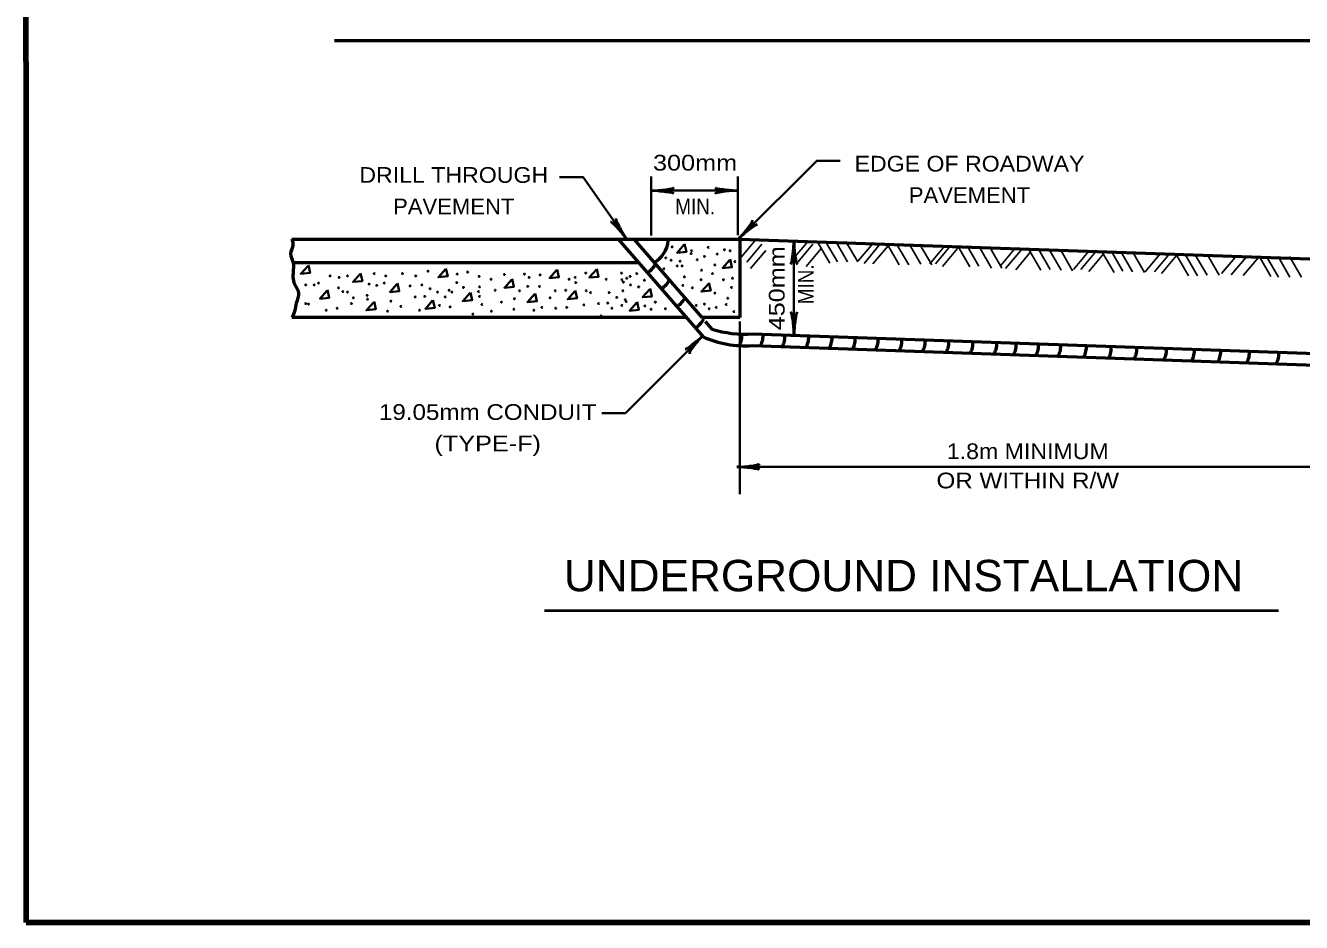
# Model space of a CAD drawing. Extents: x -90 to 623, y -379 to 75.
# Drawn here: x -42.6 to 119.8, y -369 to -254.8 of the extents above; entities that cross this region are included whole.
import ezdxf
from ezdxf.enums import TextEntityAlignment as Align

# ---------------------------------------------------------------- set-up
doc = ezdxf.new("R2010")
doc.units = 0
doc.header["$LTSCALE"] = 0.8
doc.layers.add('1', color=7, linetype='Continuous', lineweight=35)

msp = doc.modelspace()

# ---------------------------------------------------------------- linework, layer by layer
at = {"layer": '1', "lineweight": 53}
for p, q in [((-3.2295, -256.7077), (194.5145, -256.7077)), ((32.8492, -281.9895), (43.6675, -294.4345)), ((34.8368, -281.9895), (43.5093, -291.966)), ((48.3367, -281.9895), (123.3002, -284.6073)), ((-8.6632, -284.9895), (35.4571, -284.9895)), ((41.4103, -291.9895), (-8.6632, -291.9895)), ((48.3367, -291.9895), (43.5063, -291.9895)), ((43.9508, -292.4741), (44.7996, -293.4504)), ((49.9544, -294.0532), (122.8722, -296.5997)), ((49.9021, -295.5523), (122.8199, -298.0987))]:
    msp.add_line(p, q, dxfattribs=at)
at = {"layer": '1'}
for p, q in [((37.076, -281.52), (37.076, -274.02)), ((48.076, -281.5199), (48.076, -274.0199)), ((37.076, -275.8309), (48.076, -275.8309)), ((55.2352, -282.3041), (55.2352, -294.1794)), ((48.3342, -292.4785), (48.3342, -314.4785)), ((47.9859, -310.9966), (123.3332, -310.9966))]:
    msp.add_line(p, q, dxfattribs=at)
at = {"layer": '1', "lineweight": 25}
for p, q in [((50.2675, -282.2197), (48.3392, -284.518)), ((57.0807, -282.2197), (55.1523, -284.518)), ((58.2869, -282.45), (59.7869, -285.0481)), ((59.2602, -282.2878), (60.7602, -284.8858)), ((60.558, -282.2878), (62.058, -284.8858)), ((61.8558, -282.2878), (63.3558, -284.8858)), ((65.3537, -282.463), (63.4254, -284.7613)), ((51.1597, -282.6252), (49.2313, -284.9235)), ((51.6463, -283.4362), (49.718, -285.7346)), ((57.6484, -282.6252), (55.7201, -284.9235)), ((58.7028, -283.1929), (56.7745, -285.4912)), ((66.0837, -282.7874), (64.1554, -285.0858)), ((67.2193, -282.8685), (65.2909, -285.1668)), ((67.1278, -282.6933), (68.6278, -285.2914)), ((68.3445, -282.6933), (69.8445, -285.2914)), ((69.8856, -282.6122), (71.3856, -285.2102)), ((71.2644, -282.6933), (72.7644, -285.2914)), ((74.438, -282.8685), (72.5097, -285.1668)), ((75.168, -282.8685), (73.2397, -285.1668)), ((76.0602, -283.1929), (74.1318, -285.4912)), ((76.1309, -282.9366), (77.6309, -285.5347)), ((77.2665, -282.8555), (78.7665, -285.4536)), ((78.8887, -283.0988), (80.3887, -285.6969)), ((80.1864, -283.0988), (81.6864, -285.6969)), ((83.4411, -283.1118), (81.5127, -285.4102)), ((84.09, -283.4362), (82.1617, -285.7346)), ((85.3877, -283.5985), (83.4594, -285.8968)), ((85.1341, -283.3422), (86.6341, -285.9402)), ((86.3507, -283.2611), (87.8507, -285.8592)), ((87.7295, -283.3422), (89.2295, -285.9402)), ((89.1895, -283.4232), (90.6895, -286.0213)), ((92.7281, -283.5579), (90.7998, -285.8562)), ((93.6608, -283.5579), (91.7325, -285.8562)), ((94.6747, -283.8418), (92.7463, -286.1402)), ((94.4616, -283.6666), (95.9616, -286.2647)), ((95.5971, -283.5044), (97.0971, -286.1025)), ((96.8137, -283.5855), (98.3137, -286.1836)), ((98.3548, -283.6666), (99.8548, -286.2647)), ((101.8528, -283.8823), (99.9245, -286.1807)), ((103.0289, -283.8823), (101.1006, -286.1807)), ((103.9212, -284.0852), (101.9928, -286.3835)), ((103.9513, -284.0722), (105.4513, -286.6703)), ((105.0869, -284.0722), (106.5869, -286.6703)), ((106.3035, -283.9911), (107.8035, -286.5892)), ((107.8446, -283.9911), (109.3446, -286.5892)), ((111.586, -284.0852), (109.6577, -286.3835)), ((114.4145, -284.1533), (115.9145, -286.7513)), ((112.8026, -284.2473), (110.8742, -286.5457)), ((114.3437, -284.3285), (112.4153, -286.6268)), ((115.3877, -284.2343), (116.8877, -286.8324)), ((116.8477, -284.2343), (118.3477, -286.8324)), ((118.3077, -284.2343), (119.8077, -286.8324))]:
    msp.add_line(p, q, dxfattribs=at)
at = {"layer": '1', "lineweight": 40}
msp.add_line((23.5023, -329.2931), (116.8997, -329.2931), dxfattribs=at)
at = {"layer": '1', "lineweight": 158}
msp.add_line((617.1938, -368.9978), (-42.4728, -368.9978), dxfattribs=at)
msp.add_lwpolyline([(617.1938, 69.4188), (-42.5562, 69.3355), (-42.4728, -368.9978)], dxfattribs=at)
at = {"layer": '1'}
for points in [[(48.2287, -281.9152), (58.1283, -272.0157), (61.1283, -272.0157)], [(33.8785, -281.9368), (28.391, -274.0997), (25.391, -274.0997)], [(41.2724, -282.6997), (40.3511, -283.7362), (41.5411, -283.621), (41.3107, -282.6229)], [(-6.6018, -285.3831), (-7.5231, -286.4196), (-6.3331, -286.3044), (-6.5634, -285.3063)], [(10.9013, -285.81), (9.98, -286.8465), (11.17, -286.7313), (10.9397, -285.7332)], [(47.0661, -284.6513), (46.1448, -285.6877), (47.3347, -285.5726), (47.1044, -284.5745)], [(0.0457, -286.4198), (-0.8756, -287.4563), (0.3144, -287.3412), (0.0841, -286.3431)], [(19.3174, -287.1517), (18.3961, -288.1882), (19.5861, -288.073), (19.3558, -287.0749)], [(25.0501, -285.9319), (24.1288, -286.9684), (25.3187, -286.8533), (25.0884, -285.8552)], [(30.1119, -285.871), (29.1906, -286.9075), (30.3806, -286.7923), (30.1502, -285.7942)], [(-4.1623, -288.5543), (-5.0836, -289.5908), (-3.8936, -289.4757), (-4.1239, -288.4776)], [(4.7417, -287.7006), (3.8203, -288.7371), (5.0103, -288.6219), (4.78, -287.6238)], [(14.0116, -288.8592), (13.0902, -289.8957), (14.2802, -289.7806), (14.0499, -288.7825)], [(22.2447, -288.9812), (21.3234, -290.0177), (22.5134, -289.9026), (22.2831, -288.9045)], [(27.3676, -288.6153), (26.4462, -289.6518), (27.6363, -289.5367), (27.4059, -288.5386)], [(36.8814, -288.3714), (35.9601, -289.4079), (37.1501, -289.2928), (36.9198, -288.2947)], [(44.3827, -287.6396), (43.4613, -288.6761), (44.6513, -288.5609), (44.421, -287.5628)], [(1.7533, -290.018), (0.832, -291.0545), (2.022, -290.9393), (1.7917, -289.9412)], [(9.2547, -289.8351), (8.3333, -290.8716), (9.5233, -290.7564), (9.293, -289.7583)], [(35.2347, -290.079), (34.3134, -291.1155), (35.5034, -291.0003), (35.2731, -290.0023)], [(43.6774, -294.2512), (33.7779, -304.1508), (30.7779, -304.1508)]]:
    msp.add_lwpolyline(points, dxfattribs=at)
at = {"layer": '1', "lineweight": 53}
msp.add_lwpolyline([(-8.6632, -281.9895), (48.3367, -281.9895), (48.3367, -291.9895)], dxfattribs=at)
at = {"layer": '1'}
for centre in [(39.7142, -282.9907), (42.1388, -283.8394), (42.1995, -283.4757), (43.8361, -284.2031), (44.321, -283.0513), (45.4727, -283.9), (46.382, -283.3544), (47.1093, -283.4757), (38.6837, -285.7791), (38.9262, -284.3849), (39.593, -284.688), (40.381, -285.4154), (40.7447, -284.8092), (40.9872, -285.4154), (42.9268, -284.6274), (45.1697, -285.2942), (47.7155, -284.8698), (-3.8079, -286.6883), (-2.6562, -286.8702), (-1.5651, -286.6883), (1.8294, -286.3852), (3.2842, -286.6883), (5.4057, -286.3852), (7.1029, -286.6883), (8.679, -286.0822), (12.3765, -286.4458), (13.7101, -286.2034), (15.1648, -286.7489), (16.6803, -287.1127), (18.3775, -286.5065), (20.9233, -286.4458), (21.5295, -286.8702), (22.9237, -286.5671), (26.6212, -287.1127), (27.4093, -286.8702), (28.7427, -286.3246), (31.3492, -287.1127), (33.289, -286.3246), (33.3496, -287.1732), (33.9558, -286.9914), (34.3801, -286.7489), (35.2287, -286.3852), (36.1985, -287.2338), (41.2903, -286.8096), (43.4117, -287.1732), (43.4724, -285.9609), (44.8666, -286.3852), (46.2608, -287.1732), (47.4124, -286.9914), (-6.8992, -287.84), (-5.8082, -287.84), (-5.2627, -287.5976), (-2.7168, -288.2038), (-2.1713, -288.6887), (-1.5651, -288.7493), (1.1626, -287.7188), (2.1325, -287.9007), (3.1023, -287.5976), (6.3756, -287.9613), (7.891, -287.84), (8.9214, -288.3249), (9.8912, -288.7493), (11.3461, -288.5068), (11.7097, -288.7493), (12.3159, -287.5369), (13.1645, -288.1431), (15.1042, -288.6887), (15.2255, -288.0825), (17.2257, -288.5068), (20.3172, -288.5674), (21.3477, -288.0218), (22.8631, -288.0218), (24.8633, -288.5674), (26.1969, -288.5068), (27.4698, -287.5369), (28.8034, -288.5674), (29.3489, -288.8098), (31.7129, -288.8098), (33.4708, -288.5674), (33.5314, -287.4763), (34.4407, -287.84), (35.4712, -288.0825), (41.1084, -287.9007), (42.3207, -288.2038), (45.1697, -288.8705), (47.2912, -288.1431), (-6.8992, -290.204), (-6.5356, -290.2647), (-1.0802, -290.204), (-0.8377, -289.4767), (0.9202, -289.1736), (0.9808, -289.6585), (3.9509, -289.9009), (5.2238, -290.5677), (7.0423, -289.3554), (8.2547, -289.2948), (10.1337, -290.4465), (10.8612, -289.3554), (11.4672, -290.6283), (15.2255, -289.2948), (15.5286, -290.3252), (18.0137, -290.0222), (19.6504, -289.5978), (23.1662, -290.6889), (24.1966, -289.4767), (26.3182, -290.6889), (28.5003, -290.3859), (30.3794, -290.204), (31.5311, -290.1434), (32.6828, -289.416), (33.3496, -290.4465), (33.7739, -289.7191), (33.8951, -289.9616), (36.2592, -290.5071), (37.5927, -290.0222), (39.1081, -289.1736), (42.8057, -290.4465), (43.8361, -290.2647), (45.3515, -290.6889), (46.6244, -290.3252), (46.8062, -289.5372), (-4.2928, -291.0527), (-2.8987, -290.8102), (3.5267, -291.1739), (7.5879, -291.0527), (14.3768, -291.5376), (16.7408, -291.1739), (19.5898, -290.9314), (22.1357, -291.0527), (24.924, -290.8102), (30.6825, -291.78), (32.0767, -290.8102), (37.0472, -290.9314), (38.8656, -290.8708), (44.4423, -290.8708), (47.5942, -291.2345)]:
    msp.add_circle(centre, 0.0607, dxfattribs=at)
at = {"layer": '1', "lineweight": 53}
for centre, radius, start, end in [((35.4988, -281.7617), 3.7689, 301.08152, 353.13064), ((35.5578, -284.3752), 2.1707, 299.00343, 339.84739), ((37.3543, -286.3513), 2.1707, 299.00343, 339.84739), ((39.3305, -288.6269), 2.1707, 299.00343, 339.84739), ((41.6659, -291.3816), 2.1707, 299.00343, 339.84739), ((48.9237, -280.526), 13.5665, 252.30241, 274.35724), ((48.9991, -282.6433), 12.9405, 245.66897, 274.00127), ((46.4423, -294.3473), 2.1707, 327.00343, 7.84739), ((49.1371, -294.3473), 2.1707, 327.00343, 7.84739), ((51.9217, -294.4969), 2.1707, 327.00343, 7.84739), ((54.9458, -294.5269), 2.1707, 327.00343, 7.84739), ((57.9101, -294.6467), 2.1707, 327.00343, 7.84739), ((60.8743, -294.7664), 2.1707, 327.00343, 7.84739), ((63.7788, -294.8563), 2.1707, 327.00343, 7.84739), ((66.8028, -295.006), 2.1707, 327.00343, 7.84739), ((69.7671, -295.0959), 2.1707, 327.00343, 7.84739), ((72.7913, -295.1857), 2.1707, 327.00343, 7.84739), ((75.8453, -295.3354), 2.1707, 327.00343, 7.84739), ((78.8994, -295.3354), 2.1707, 327.00343, 7.84739), ((81.3547, -295.515), 2.1707, 327.00343, 7.84739), ((84.1992, -295.6049), 2.1707, 327.00343, 7.84739), ((87.0137, -295.6947), 2.1707, 327.00343, 7.84739), ((90.2773, -295.8144), 2.1707, 327.00343, 7.84739), ((93.4512, -295.9342), 2.1707, 327.00343, 7.84739), ((96.7148, -296.024), 2.1707, 327.00343, 7.84739), ((100.4875, -296.1438), 2.1707, 327.00343, 7.84739), ((104.0207, -296.2935), 2.1707, 327.00343, 7.84739), ((107.3742, -296.3834), 2.1707, 327.00343, 7.84739), ((111.0271, -296.5331), 2.1707, 327.00343, 7.84739), ((114.7698, -296.6529), 2.1707, 327.00343, 7.84739)]:
    msp.add_arc(centre, radius, start, end, dxfattribs=at)
at = {"layer": '1', "lineweight": 40}
for centre, major_axis, ratio, start_param, end_param in [((38.1965, -276.0425), (1.7565, -0.1757), 0.07063, 6.28230741, 8.55970261), ((38.1965, -276.0425), (1.7565, -0.1757), 0.07063, 6.28230741, 8.55970261), ((38.1672, -275.5546), (-1.7857, -0.1562), 0.122415, 0.89635335, 3.14159265), ((38.1672, -275.5546), (-1.7857, -0.1562), 0.122415, 0.89635335, 3.14159265), ((46.9848, -276.1072), (1.7857, 0.1562), 0.122415, 0.89635335, 3.14159265), ((46.9848, -276.1072), (1.7857, 0.1562), 0.122415, 0.89635335, 3.14159265), ((46.9555, -275.6193), (1.7565, -0.1757), 0.07063, 3.14071475, 5.41810995), ((46.9555, -275.6193), (1.7565, -0.1757), 0.07063, 3.14071475, 5.41810995), ((33.0263, -281.2014), (1.1521, -1.3732), 0.122415, 0.89635335, 3.14159265), ((33.4091, -280.8975), (-0.8636, 1.5396), 0.07063, 6.28230741, 8.55970261), ((48.805, -280.9482), (-1.1523, -1.3731), 0.122415, 0.89635335, 3.14159265), ((48.805, -280.9482), (-1.1523, -1.3731), 0.122415, 0.89635335, 3.14159265), ((49.1707, -281.2725), (1.3662, 1.1178), 0.07063, 6.28230741, 8.55970261), ((49.1707, -281.2725), (1.3662, 1.1178), 0.07063, 6.28230741, 8.55970261), ((55.0236, -283.4246), (-0.1757, -1.7565), 0.07063, 6.28230741, 8.55970261), ((55.0236, -283.4246), (-0.1757, -1.7565), 0.07063, 6.28230741, 8.55970261), ((55.5115, -283.3953), (-0.1562, 1.7857), 0.122415, 0.89635335, 3.14159265), ((55.5115, -283.3953), (-0.1562, 1.7857), 0.122415, 0.89635335, 3.14159265), ((54.9589, -293.0882), (0.1562, -1.7857), 0.122415, 0.89635335, 3.14159265), ((54.9589, -293.0882), (0.1562, -1.7857), 0.122415, 0.89635335, 3.14159265), ((55.4468, -293.0589), (0.1757, 1.7565), 0.07063, 6.28230741, 8.55970261), ((55.4468, -293.0589), (0.1757, 1.7565), 0.07063, 6.28230741, 8.55970261), ((42.7355, -294.8939), (1.3662, 1.1178), 0.07063, 3.14071475, 5.41810995), ((43.1012, -295.2182), (1.1523, 1.3731), 0.122415, 0.89635335, 3.14159265), ((49.1064, -311.2082), (1.7565, -0.1757), 0.07063, 6.28230741, 8.55970261), ((49.0771, -310.7203), (-1.7857, -0.1562), 0.122415, 0.89635335, 3.14159265)]:
    msp.add_ellipse(centre, major_axis=major_axis, ratio=ratio, start_param=start_param, end_param=end_param, dxfattribs=at)
at = {"layer": '1', "lineweight": 53}
msp.add_spline([(-8.6632, -281.9895), (-8.5245, -282.726), (-8.8239, -283.8637), (-8.5245, -284.8818), (-8.4646, -285.6602), (-8.4047, -287.5167), (-7.8059, -288.8341), (-8.1053, -290.1515), (-8.285, -291.1097), (-8.6632, -291.9895)], degree=3, dxfattribs=at)

# ---------------------------------------------------------------- texts
at = {"layer": '1'}
for s, height, width, p in [('300mm', 2, 1.2, (37.3015, -273.2717)), ('MIN.', 2, 0.9, (40.1268, -278.8589)), ('1.8m MINIMUM', 2, 1.1, (74.6907, -310.005)), ('OR WITHIN R/W', 2, 1.15, (73.3732, -313.7283)), ('UNDERGROUND INSTALLATION', 4, 1.05, (25.9601, -326.8357))]:
    msp.add_text(s, height=height, dxfattribs=dict(at, width=width)).set_placement(p)
for s, width, p in [('EDGE OF ROADWAY', 1.1, (77.572, -273.3993)), ('DRILL THROUGH', 1.1, (11.9392, -274.8365)), ('PAVEMENT', 1.05, (77.572, -277.3993)), ('PAVEMENT', 1.05, (11.9392, -278.8365)), ('19.05mm CONDUIT', 1.15, (16.2591, -305.0143)), ('(TYPE-F)', 1.2, (16.259, -309.0143))]:
    msp.add_text(s, height=2, dxfattribs=dict(at, width=width)).set_placement(p, align=Align.CENTER)
for s, width, p in [('450mm', 1.2, (54.0448, -293.6137)), ('MIN.', 0.9, (57.7504, -290.2978))]:
    msp.add_text(s, height=2, rotation=90, dxfattribs=dict(at, width=width)).set_placement(p)

doc.saveas('drawing.dxf')
